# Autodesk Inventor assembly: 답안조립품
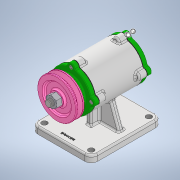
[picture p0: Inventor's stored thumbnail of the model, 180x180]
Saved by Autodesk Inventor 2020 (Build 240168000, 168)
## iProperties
Created: 2022-11
Part Number: 답안조립품
Document SubType Name: Assembly
Designer: owner
Author: owner
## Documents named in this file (12)
- C:\Users\owner\Desktop\721108V1001\답안조립품.iam
- C:\Users\owner\Desktop\721108V1001\본체.ipt
- C:\Users\owner\Desktop\721108V1001\V-벨트풀리.ipt
- C:\Users\owner\Desktop\721108V1001\개스킷.ipt
- C:\Users\owner\Desktop\721108V1001\너트 M12 x 1.25.ipt
- C:\Users\owner\Desktop\721108V1001\뒤커버.ipt
- C:\Users\owner\Desktop\721108V1001\베어링 6204.ipt
- C:\Users\owner\Desktop\721108V1001\볼트 M4 x 12.ipt
- C:\Users\owner\Desktop\721108V1001\앞커버.ipt
- C:\Users\owner\Desktop\721108V1001\오일 실.ipt
- C:\Users\owner\Desktop\721108V1001\축.ipt
- C:\Users\owner\Desktop\721108V1001\키 4 x 4.ipt
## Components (7 placed, 6 different names)
1. V-벨트풀리:1
2. 개스킷:1
3. KS B 1012 클래스 1 일반 - 미터 M12x1.25:1
4. KS B 2023 6204 - 20 x 47 x 14:1
5. KS B 2804 D D - 20 32 8:1
6. KS B 1311 (I) 4 x 4 x 12:1
7. 개스킷:2
